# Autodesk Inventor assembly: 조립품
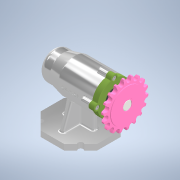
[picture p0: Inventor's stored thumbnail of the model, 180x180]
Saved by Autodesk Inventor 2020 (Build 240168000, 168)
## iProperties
Created: 2021-01
Part Number: 조립품
Document SubType Name: Assembly
Designer: PC2-13
Author: PC2-13
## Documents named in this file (12)
- C:\Users\PC2-13\Desktop\710106V1024\조립품.iam
- C:\Users\PC2-13\Desktop\710106V1024\본체.ipt
- C:\Users\PC2-13\Desktop\710106V1024\커버.ipt
- C:\Users\PC2-13\Desktop\710106V1024\베어링 6004.ipt
- C:\Users\PC2-13\Desktop\710106V1024\축.ipt
- C:\Users\PC2-13\Desktop\710106V1024\오일 실.ipt
- C:\Users\PC2-13\Desktop\710106V1024\볼트 M4.ipt
- C:\Users\PC2-13\Desktop\710106V1024\어댑터슬리브.ipt
- C:\Users\PC2-13\Desktop\710106V1024\베어링 51202.ipt
- C:\Users\PC2-13\Desktop\710106V1024\키 5 x 5 x 14.ipt
- C:\Users\PC2-13\Desktop\710106V1024\스프로킷.ipt
- C:\Users\PC2-13\Desktop\710106V1024\멈춤나사 M3.ipt
